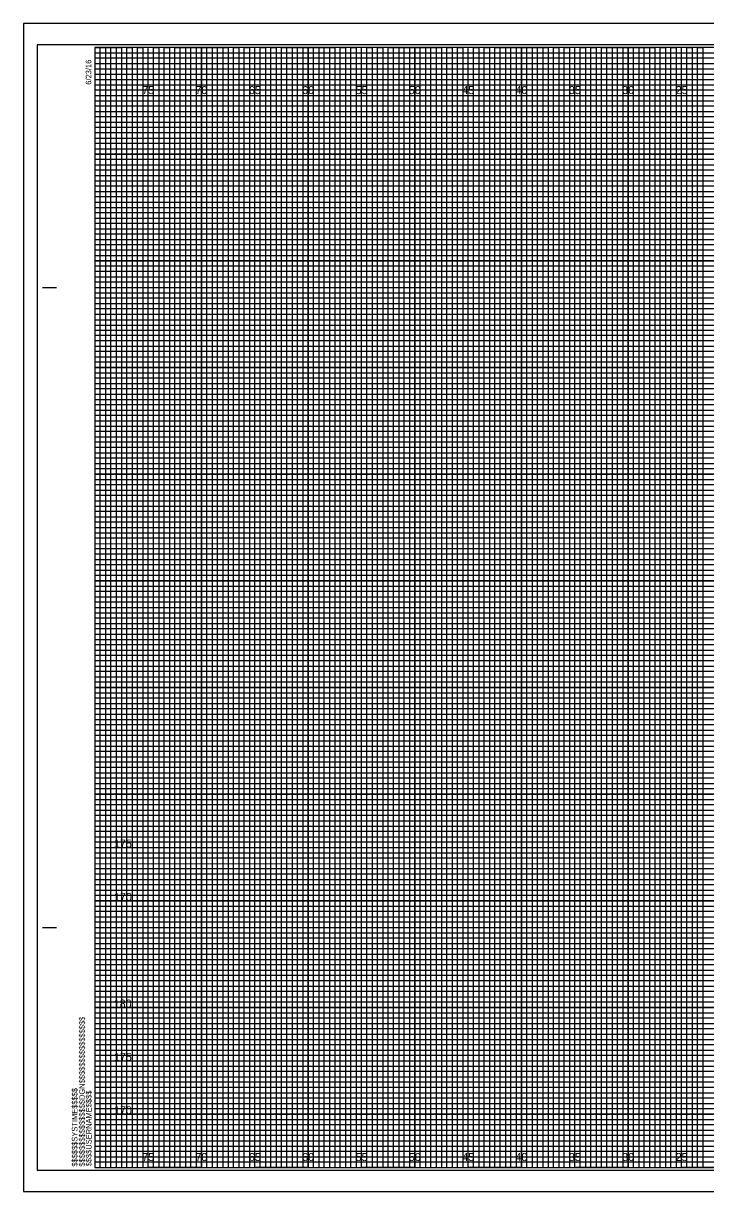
# Model space of a CAD drawing. Extents: x -7 to 162, y -2 to 767.
# Drawn here: x -6.7 to 57.2, y 657.8 to 767.2 of the extents above; entities that cross this region are included whole.
import ezdxf

# ---------------------------------------------------------------- set-up
doc = ezdxf.new("R2010")
doc.units = 0
for name, color, linetype in [('Exist Cross Section Cell', 7, 'Continuous'), ('Prop CMT Pvmt Course 1', 7, 'Continuous'), ('Prop CMT Pvmt Course 1 Wedge', 7, 'Continuous'), ('Prop CMT Pvmt Course 2', 7, 'Continuous'), ('Prop CMT Pvmt Course 3', 7, 'Continuous'), ('Prop CMT Pvmt Surface Shoulder', 7, 'Continuous'), ('Prop CMT Shld Paved Course 2', 7, 'Continuous'), ('Prop CMT Shld Paved Course 3', 7, 'Continuous'), ('Prop CMT Slope Grass', 7, 'Continuous'), ('Prop CMT Subgrade Earthwork', 7, 'Continuous'), ('Scratch_Level_0', 7, 'Continuous')]:
    doc.layers.add(name, color=color, linetype=linetype)

msp = doc.modelspace()

# ---------------------------------------------------------------- linework, layer by layer
at = {"layer": 'Prop CMT Pvmt Course 1'}
for p, q in [((0, 764.5), (130, 764.5)), ((130, 763.99), (0, 763.99)), ((0, 763.99), (0, 763.5)), ((0, 763.5), (130, 763.5)), ((130, 762.95), (0, 762.95)), ((0, 762.95), (0, 762)), ((0, 762), (160, 762))]:
    msp.add_line(p, q, dxfattribs=at)
for points in [[(0, 761.5), (135, 761.5), (160, 761.5), (160, 761), (0, 761)], [(0, 760.5), (160, 760.5), (160, 759.5), (0, 759.5)], [(0, 759), (160, 759), (160, 758.5), (0, 758.49)], [(0, 758), (160, 758), (160, 757), (0, 757)], [(0, 756.5), (160, 756.5), (160, 756), (0, 756)], [(0, 755.5), (160, 755.5), (160, 754.5), (0, 754.5)], [(0, 754), (160, 754), (160, 753.5), (0, 753.5)], [(0, 753), (160, 753), (160, 752), (0, 752)], [(0, 751.5), (160, 751.5), (160, 751), (0, 751)], [(0, 750.5), (160, 750.5), (160, 749.5), (0, 749.5)], [(0, 749), (160, 749), (160, 748.5), (0, 748.5)], [(0, 748), (160, 748), (160, 746.98), (160, 746.5), (160, 746), (0, 746)], [(0, 747), (160, 747), (160, 746.5), (0, 746.5)], [(0, 745.5), (160, 745.5), (160, 744.5), (0, 744.51)], [(0, 744.51), (160, 744.5), (160, 744), (0, 744)], [(0, 743.5), (160, 743.5), (160, 743), (0, 743)], [(0, 742), (160, 742), (160, 741.5), (0, 741.5)], [(0, 741), (160, 741), (160, 740.5), (0, 740.5)], [(-0.04, 739.45), (160, 739.45), (160, 738.94), (-0.04, 738.94)], [(0, 738.5), (160, 738.5), (160, 738), (0, 738)], [(0, 737), (160, 737), (160, 736.5), (0, 736.5)], [(0, 736), (160, 736), (160, 735.5), (0, 735.5)], [(0, 734.5), (160, 734.5), (160, 734), (0, 734)], [(0, 733.5), (160, 733.5), (160, 733), (0, 733)], [(0, 732), (160, 732), (160, 731.5), (0, 731.5)], [(0, 731), (160, 731), (160, 730.5), (0, 730.5)], [(0, 729.5), (160, 729.5), (160, 728.99), (0, 729)], [(0, 728.5), (160, 728.5), (160, 728), (0, 728)], [(0, 727), (160, 727), (160, 726.5), (0, 726.5)], [(0, 726), (160, 726), (160, 725.5), (0, 725.5)], [(0, 724.5), (160, 724.5), (160, 724), (0, 724)], [(0, 723.5), (160, 723.5), (160, 723), (0, 723)], [(0, 722), (160, 722), (160, 721.5), (0, 721.5)], [(0, 721), (160, 721), (160, 720.5), (0, 720.5)], [(0, 719.5), (160, 719.5), (160, 719), (0, 719)], [(0, 718.5), (160.03, 718.46), (160, 718), (0, 718)], [(0, 717), (160, 717), (160, 716.5), (0, 716.5)], [(0, 716), (160, 716), (160, 715.5), (0, 715.5)], [(0, 714.5), (160, 714.5), (160, 714), (0, 714)], [(0, 713.5), (160, 713.5), (160, 713), (0, 713)], [(0, 712), (160, 712), (160, 711.5), (0, 711.5)], [(0, 711), (160, 711), (160, 710.5), (0, 710.5)], [(0, 709.5), (160, 709.5), (160, 709), (0, 709)], [(0, 708.5), (160, 708.5), (160, 708), (0, 708)], [(0, 707), (160, 707), (160, 706.5), (0, 706.5)], [(0, 706), (160, 706), (160, 705.5), (0, 705.5)], [(0, 704.5), (160, 704.5), (160, 704), (0, 704)], [(0, 703.5), (160, 703.5), (160, 703), (0, 703)], [(0, 702), (160, 702), (160, 701.5), (0, 701.5)], [(0, 701), (160, 701), (160, 700.5), (0, 700.5)], [(0, 699.5), (160, 699.5), (160, 698.99), (0, 699)], [(0, 698.5), (160, 698.5), (160, 698), (0, 698)], [(0, 697), (160, 697), (160, 696.5), (0, 696.5)], [(0, 696), (160, 696), (160, 695.5), (0, 695.5)], [(0, 694.5), (160, 694.5), (160, 694), (0, 694)], [(0, 693.5), (160, 693.5), (160, 693), (0, 693)], [(0, 692), (160, 692), (160, 691.5), (0, 691.5)], [(0, 691), (160, 691), (160, 690.5), (0, 690.5)], [(0, 689.5), (160, 689.5), (160, 689), (0, 689)], [(0, 688.5), (160.03, 688.46), (160, 688), (0, 688)], [(0, 687), (160, 687), (160, 686.5), (0, 686.5)], [(0, 686), (160, 686), (160, 685.5), (0, 685.5)], [(0, 684.5), (160, 684.5), (160, 684), (0, 684)], [(0, 683.5), (160, 683.5), (160, 683), (0, 683)], [(0, 682), (160, 682), (160, 681.5), (0, 681.5)], [(0, 681), (160, 681), (160, 680.5), (0, 680.5)], [(0, 679.5), (160, 679.5), (160, 679), (0, 679)], [(0, 678.5), (160, 678.5), (160, 678), (0, 678)], [(0, 677), (160, 677), (160, 676.5), (0, 676.5)], [(0, 676), (160, 676), (160, 675.5), (0, 675.5)], [(0, 674.5), (160, 674.5), (160, 674), (0, 674)], [(0, 673.5), (160, 673.5), (160, 673), (0, 673)], [(0, 672), (160, 672), (160, 671.5), (0, 671.5)], [(0, 671), (160, 671), (160, 670.5), (0, 670.5)], [(0, 669.5), (160, 669.5), (160, 669), (0, 669)], [(0, 668.5), (160, 668.5), (160, 668), (0, 668)], [(0, 667), (160, 667), (160, 666.5), (0, 666.5)], [(0, 666), (160, 666), (160, 665.5), (0, 665.5)], [(0, 664.5), (160, 664.5), (160, 664), (0, 664)], [(0, 663.5), (160, 663.5), (160, 663), (0, 663)], [(0, 662), (160, 662), (160, 661.5), (0, 661.5)], [(0, 661), (160, 661), (160, 660.5), (0, 660.5)]]:
    msp.add_lwpolyline(points, dxfattribs=at)
at = {"layer": 'Prop CMT Pvmt Course 2'}
for p, q in [((5, 660), (5, 765)), ((10, 660), (10, 765)), ((15, 660), (15, 765)), ((20, 660), (20, 765)), ((25, 660), (25, 765)), ((30, 660), (30, 765)), ((35, 660), (35, 765)), ((40, 660), (40, 765)), ((45, 660), (45, 765)), ((50, 660), (50, 765)), ((55, 660), (55, 765)), ((0, 760), (160, 760)), ((0, 755), (160, 755)), ((0, 750), (160, 750)), ((0, 745), (160, 745)), ((0, 740), (160, 740)), ((0, 735), (160, 735)), ((0, 730), (160, 730)), ((0, 725), (160, 725)), ((0, 720), (160, 720)), ((0, 715), (160, 715)), ((0, 710), (160, 710)), ((0, 705), (160, 705)), ((0, 700), (160, 700)), ((0, 695), (160, 695)), ((0, 690), (160, 690)), ((0, 685), (160, 685)), ((0, 680), (160, 680)), ((0, 675), (160, 675)), ((0, 670), (160, 670)), ((0, 665), (160, 665))]:
    msp.add_line(p, q, dxfattribs=at)
at = {"layer": 'Prop CMT Pvmt Course 3'}
for p, q in [((161.65, 767.25), (-6.7, 767.25)), ((-6.7, 767.25), (-6.7, 657.75)), ((-6.7, 657.75), (161.65, 657.75))]:
    msp.add_line(p, q, dxfattribs=at)
at = {"layer": 'Prop CMT Pvmt Surface Shoulder'}
for points in [[(0, 765), (2.5, 765), (2.5, 660), (7.5, 660), (7.5, 765), (12.5, 765), (12.5, 660), (17.5, 660), (17.5, 765), (22.5, 765), (22.5, 660), (27.5, 660), (27.5, 765), (32.5, 765), (32.5, 660), (37.5, 660), (37.5, 765), (42.5, 765), (42.5, 660), (47.5, 660), (47.5, 765), (52.5, 765), (52.5, 660), (57.5, 660)], [(0, 762.5), (137.5, 762.5)], [(0, 752.5), (160, 752.5), (160, 757.5), (0, 757.5)], [(0, 742.5), (160, 742.5), (160, 747.5), (0, 747.5)], [(0, 732.5), (160, 732.5), (160, 737.5), (0, 737.5)], [(0, 722.5), (160, 722.5), (160, 727.5), (0, 727.5)], [(0, 712.5), (160, 712.5), (160, 717.5), (0, 717.5)], [(0, 702.5), (160, 702.5), (160, 707.5), (0, 707.5)], [(0, 692.5), (160, 692.5), (160, 697.5), (0, 697.5)], [(0, 682.5), (160, 682.5), (160, 687.5), (0, 687.5)], [(0, 672.5), (160, 672.5), (160, 677.5), (0, 677.5)], [(0, 662.5), (160, 662.5), (160, 667.5), (0, 667.5)]]:
    msp.add_lwpolyline(points, dxfattribs=at)
at = {"layer": 'Prop CMT Shld Paved Course 2'}
msp.add_lwpolyline([(-6.7, 657.75), (161.65, 657.75), (161.65, 767.25), (-6.7, 767.25)], close=True, dxfattribs=at)
at = {"layer": 'Prop CMT Shld Paved Course 3'}
msp.add_lwpolyline([(-5.4, 659.75), (161.2, 659.75), (161.2, 765.25), (-5.4, 765.25)], close=True, dxfattribs=at)
at = {"layer": 'Prop CMT Slope Grass'}
for points in [[(0, 660), (0.5, 660), (0.5, 765), (1, 765), (1, 660)], [(1, 660), (1.5, 660), (1.5, 765), (2, 765), (2, 660)], [(2.5, 660), (3, 660), (3, 765), (3.5, 765), (3.5, 660)], [(3.5, 660), (4, 660), (4, 765), (4.5, 765), (4.5, 660)], [(5, 660), (5.5, 660), (5.5, 765), (6, 765), (6, 660)], [(6, 660), (6.5, 660), (6.5, 765), (7, 765), (7, 660)], [(7.5, 660), (8, 660), (8, 765), (8.5, 765), (8.5, 660)], [(8.5, 660), (9, 660), (9, 765), (9.5, 765), (9.5, 660)], [(10, 660), (10.5, 660), (10.5, 765), (11, 765), (11, 660)], [(11, 660), (11.5, 660), (11.5, 765), (12, 765), (12, 660)], [(12.5, 660), (13, 660), (13, 765), (13.5, 765), (13.5, 660)], [(13.5, 660), (14, 660), (14, 765), (14.5, 765), (14.5, 660)], [(15, 660), (15.5, 660), (15.5, 765), (16, 765), (16, 660)], [(16, 660), (16.5, 660), (16.5, 765), (17, 765), (17, 660)], [(17.5, 660), (18, 660), (18, 765), (18.5, 765), (18.5, 660)], [(18.5, 660), (19, 660), (19, 765), (19.5, 765), (19.5, 660)], [(20, 660), (20.5, 660), (20.5, 765), (21, 765), (21, 660)], [(21, 660), (21.5, 660), (21.5, 765), (22, 765), (22, 660)], [(22.5, 660), (23, 660), (23, 765), (23.5, 765), (23.5, 660)], [(23.5, 660), (24, 660), (24, 765), (24.5, 765), (24.5, 660)], [(25, 660), (25.5, 660), (25.5, 765), (26, 765), (26, 660)], [(26, 660), (26.5, 660), (26.5, 765), (27, 765), (27, 660)], [(27.5, 660), (28, 660), (28, 765), (28.5, 765), (28.5, 660)], [(28.5, 660), (29, 660), (29, 765), (29.5, 765), (29.5, 660)], [(30, 660), (30.5, 660), (30.5, 765), (31, 765), (31, 660)], [(31, 660), (31.5, 660), (31.5, 765), (32, 765), (32, 660)], [(32.5, 660), (33, 660), (33, 765), (33.5, 765), (33.5, 660)], [(33.5, 660), (34, 660), (34, 765), (34.5, 765), (34.5, 660)], [(35, 660), (35.5, 660), (35.5, 765), (36, 765), (36, 660)], [(36, 660), (36.5, 660), (36.5, 765), (37, 765), (37, 660)], [(37.5, 660), (38, 660), (38, 765), (38.5, 765), (38.5, 660)], [(38.5, 660), (39, 660), (39, 765), (39.5, 765), (39.5, 660)], [(40, 660), (40.5, 660), (40.5, 765), (41, 765), (41, 660)], [(41, 660), (41.5, 660), (41.5, 765), (42, 765), (42, 660)], [(42.5, 660), (43, 660), (43, 765), (43.5, 765), (43.5, 660)], [(43.5, 660), (44, 660), (44, 765), (44.5, 765), (44.5, 660)], [(45, 660), (45.5, 660), (45.5, 765), (46, 765), (46, 660)], [(46, 660), (46.5, 660), (46.5, 765), (47, 765), (47, 660)], [(47.5, 660), (48, 660), (48, 765), (48.5, 765), (48.5, 660)], [(48.5, 660), (49, 660), (49, 765), (49.5, 765), (49.5, 660)], [(50, 660), (50.5, 660), (50.5, 765), (51, 765), (51, 660)], [(51, 660), (51.5, 660), (51.5, 765), (52, 765), (52, 660)], [(52.5, 660), (53, 660), (53, 765), (53.5, 765), (53.5, 660)], [(53.5, 660), (54, 660), (54, 765), (54.5, 765), (54.5, 660)], [(55, 660), (55.5, 660), (55.5, 765), (56, 765), (56, 660)], [(56, 660), (56.5, 660), (56.5, 765), (57, 765), (57, 660)]]:
    msp.add_lwpolyline(points, dxfattribs=at)
at = {"layer": 'Prop CMT Subgrade Earthwork'}
for p, q in [((-4.9, 742.5), (-3.65, 742.5)), ((-4.85, 742.5), (-3.6, 742.5)), ((-4.9, 682.5), (-3.65, 682.5)), ((-4.85, 682.5), (-3.6, 682.5)), ((0, 660), (0, 660)), ((0, 660), (0, 660)), ((0, 660), (0, 660)), ((0, 660), (0, 660)), ((0, 660), (0, 660)), ((0, 660), (0, 660)), ((0, 660), (0, 660))]:
    msp.add_line(p, q, dxfattribs=at)
msp.add_lwpolyline([(160, 765), (0, 765), (0, 660), (160, 660)], close=True, dxfattribs=at)
at = {"layer": 'Scratch_Level_0'}
for p, q in [((5, 765), (0, 765)), ((5, 660), (5, 765)), ((15, 765), (10, 765)), ((10, 765), (10, 660)), ((15, 660), (15, 765)), ((25, 765), (20, 765)), ((20, 765), (20, 660)), ((25, 660), (25, 765)), ((35, 765), (30, 765)), ((30, 765), (30, 660)), ((35, 660), (35, 765)), ((45, 765), (40, 765)), ((40, 765), (40, 660)), ((45, 660), (45, 765)), ((55, 765), (50, 765)), ((50, 765), (50, 660)), ((55, 660), (55, 765)), ((10, 660), (5, 660)), ((20, 660), (15, 660)), ((30, 660), (25, 660)), ((40, 660), (35, 660)), ((50, 660), (45, 660)), ((60, 660), (55, 660))]:
    msp.add_line(p, q, dxfattribs=at)
for points in [[(0, 760), (160, 760), (160, 755), (0, 755)], [(0, 750), (160, 750), (160, 745), (0, 745)], [(0, 740), (160, 740), (160, 735), (0, 735)], [(0, 730), (160, 730), (160, 725), (0, 725)], [(0, 720), (160, 720), (160, 715), (0, 715)], [(0, 710), (160, 710), (160, 705), (0, 705)], [(0, 700), (160, 700), (160, 695), (0, 695)], [(0, 690), (160, 690), (160, 685), (0, 685)], [(0, 680), (160, 680), (160, 675), (0, 675)], [(0, 670), (160, 670), (160, 665), (0, 665)]]:
    msp.add_lwpolyline(points, dxfattribs=at)

# ---------------------------------------------------------------- texts
at = {"layer": 'Exist Cross Section Cell'}
for s, p in [('75', (4.44, 760.62)), ('70', (9.43, 760.62)), ('65', (14.44, 760.62)), ('60', (19.43, 760.62)), ('55', (24.44, 760.62)), ('50', (29.43, 760.62)), ('45', (34.44, 760.62)), ('40', (39.43, 760.62)), ('35', (44.44, 760.62)), ('30', (49.43, 760.62)), ('25', (54.44, 760.62)), ('70', (9.43, 660.62)), ('65', (14.44, 660.62)), ('60', (19.43, 660.62)), ('50', (29.43, 660.62)), ('40', (39.43, 660.62)), ('35', (44.44, 660.62)), ('30', (49.43, 660.62)), ('25', (54.44, 660.62)), ('75', (4.44, 660.62)), ('55', (24.44, 660.62)), ('45', (34.44, 660.62))]:
    msp.add_text(s, height=0.75, dxfattribs=at).set_placement(p)
at = {"layer": 'Prop CMT Pvmt Course 1 Wedge'}
for s, p in [('175', (1.79, 690)), ('170', (1.8, 685)), ('180', (1.77, 675)), ('175', (1.79, 670)), ('170', (1.8, 665))]:
    msp.add_text(s, height=0.75, dxfattribs=at).set_placement(p)
at = {"layer": 'Prop CMT Subgrade Earthwork'}
for s, p in [('6/23/16', (-0.33, 761.5)), ('$$$$$$$$$$$$$$$$DGN$$$$$$$$$$$$$$$$', (-0.94, 660.09)), ('$$$$$$SYSTIME$$$$$', (-1.63, 660.09)), ('$$$$USERNAME$$$$', (-0.31, 660.12))]:
    msp.add_text(s, height=0.525, rotation=90, dxfattribs=at).set_placement(p)

doc.saveas('drawing.dxf')
